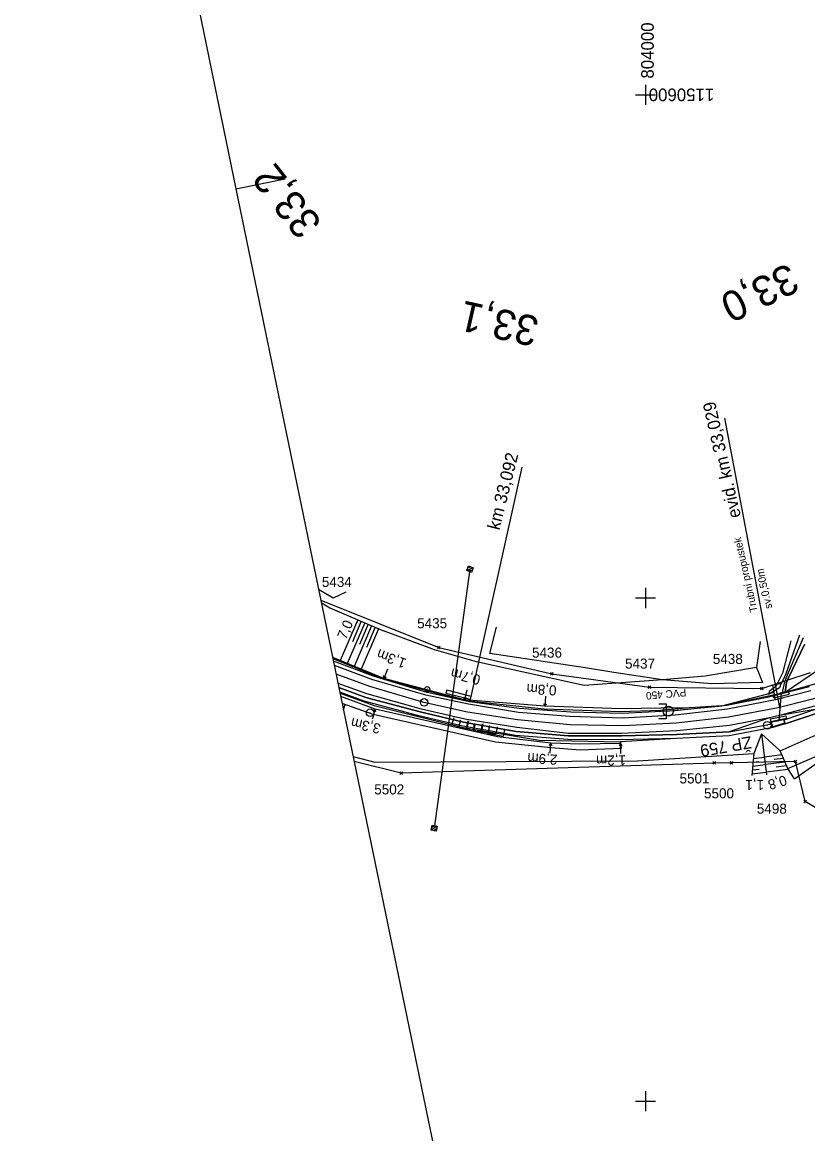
# Model space of a CAD drawing. Extents: x -804166 to -803706, y -1151030 to -1150147.
# Drawn here: x -804123.8 to -803967.8, y -1150806.5 to -1150585.6 of the extents above; entities that cross this region are included whole.
import ezdxf

# ---------------------------------------------------------------- set-up
doc = ezdxf.new("R2010")
doc.units = 0
for name, color, linetype in [('0381KM032-037P - Vrstva 1', 7, 'Continuous'), ('0381KM032-037P - Vrstva 11', 7, 'Continuous'), ('0381KM032-037P - Vrstva 13', 7, 'Continuous'), ('0381KM032-037P - Vrstva 16', 7, 'Continuous'), ('0381KM032-037P - Vrstva 17', 7, 'Continuous'), ('0381KM032-037P - Vrstva 19', 7, 'Continuous'), ('0381KM032-037P - Vrstva 25', 7, 'Continuous'), ('0381KM032-037P - Vrstva 4', 7, 'Continuous'), ('0381KM032-037P - Vrstva 43', 7, 'Continuous'), ('0381KM032-037P - Vrstva 44', 7, 'Continuous'), ('0381KM032-037P - Vrstva 48', 7, 'Continuous'), ('0381KM032-037P - Vrstva 49', 7, 'Continuous'), ('0381KM032-037P - Vrstva 7', 7, 'Continuous'), ('0381KM032-037P - Vrstva 9', 7, 'Continuous'), ('formát', 7, 'Continuous'), ('krizky_1000 - souradnice', 7, 'Continuous'), ('krizky_1000 - Vrstva 1', 7, 'Continuous'), ('szdc - hran DP', 7, 'Continuous'), ('szdc - szdc_cislo', 7, 'Continuous'), ('szdc - szdc_krizek', 7, 'Continuous'), ('vyt_sit - stávající', 7, 'Continuous')]:
    doc.layers.add(name, color=color, linetype=linetype)

msp = doc.modelspace()

# ---------------------------------------------------------------- linework, layer by layer
at = {"layer": '0381KM032-037P - Vrstva 1'}
msp.add_lwpolyline([(-803901.91, -1150682.6), (-803910.01, -1150690), (-803918.64, -1150696.78), (-803928.04, -1150703.06), (-803937.95, -1150708.69), (-803946.8, -1150712.93), (-803956.66, -1150716.87), (-803966.85, -1150720.1), (-803973.69, -1150721.81), (-803983.51, -1150723.68), (-803993.92, -1150724.91), (-804004.46, -1150725.42), (-804014.95, -1150725.21), (-804025.47, -1150724.25), (-804035.41, -1150722.67), (-804044.08, -1150720.74), (-804054.77, -1150717.61), (-804061.47, -1150715.14)], dxfattribs=at)
at = {"layer": '0381KM032-037P - Vrstva 11'}
for p, q in [((-804034.26, -1150693.99), (-804035.54, -1150694.57)), ((-804034.75, -1150693.8), (-804035.36, -1150694.08)), ((-804034.44, -1150694.48), (-804035.04, -1150694.76)), ((-804041.41, -1150745.38), (-804042.6, -1150746.13)), ((-804041.93, -1150745.26), (-804042.49, -1150745.62)), ((-804041.53, -1150745.9), (-804042.08, -1150746.25))]:
    msp.add_line(p, q, dxfattribs=at)
for points in [[(-804034.6, -1150694.92), (-804035.54, -1150694.57), (-804035.19, -1150693.64), (-804034.25, -1150693.98)], [(-804041.63, -1150746.35), (-804042.61, -1150746.13), (-804042.39, -1150745.16), (-804041.41, -1150745.38)]]:
    msp.add_lwpolyline(points, close=True, dxfattribs=at)
at = {"layer": '0381KM032-037P - Vrstva 13'}
for p, q in [((-804051.27, -1150714.14), (-804052.03, -1150715.99)), ((-804035.82, -1150720.44), (-804051.93, -1150716.22)), ((-804035.5, -1150718.26), (-804035.97, -1150720.21)), ((-804019.87, -1150719.5), (-804020.03, -1150721.49)), ((-804054.2, -1150724.02), (-804053.75, -1150722.07)), ((-803974.7, -1150725.77), (-803974.91, -1150725)), ((-803972.34, -1150724.85), (-803974.74, -1150725.59)), ((-803974.74, -1150725.59), (-803974.7, -1150725.77)), ((-803972.29, -1150725.01), (-803974.7, -1150725.77)), ((-803972.54, -1150724.23), (-803972.54, -1150724.26)), ((-803972.54, -1150724.26), (-803972.29, -1150725.01)), ((-803972.34, -1150724.85), (-803972.29, -1150725.01)), ((-804018.95, -1150730.84), (-804018.83, -1150728.85)), ((-804004.99, -1150728.9), (-804004.87, -1150729.93)), ((-804004.95, -1150730.9), (-804004.99, -1150728.9))]:
    msp.add_line(p, q, dxfattribs=at)
for points in [[(-803902.54, -1150686.99), (-803908.53, -1150691.68), (-803917.54, -1150698.65), (-803926.89, -1150705.06), (-803937, -1150710.49), (-803946.02, -1150714.66), (-803956.26, -1150718.85), (-803966.29, -1150722.19), (-803972.54, -1150724.26)], [(-803972.29, -1150725.01), (-803966.12, -1150722.97), (-803955.96, -1150719.58), (-803945.71, -1150715.38), (-803936.57, -1150711.19), (-803926.51, -1150705.78), (-803917.07, -1150699.31), (-803908.04, -1150692.29), (-803902.09, -1150687.65)], [(-804052.03, -1150715.99), (-804062.15, -1150711.83)], [(-804062.12, -1150712.02), (-804052.3, -1150716.03), (-804051.93, -1150716.22)], [(-804052.11, -1150715.42), (-804052.03, -1150715.99), (-804051.56, -1150715.64)], [(-803991.2, -1150721.8), (-803996.89, -1150721.92), (-804004.84, -1150722.06), (-804020.03, -1150721.49), (-804035.97, -1150720.21), (-804052.03, -1150715.99)], [(-804060.92, -1150717.79), (-804055.61, -1150719.76), (-804044.75, -1150722.66), (-804036.16, -1150724.67), (-804025.7, -1150726.54), (-804015.38, -1150727.38), (-804004.78, -1150727.4), (-803993.85, -1150727.11), (-803983.42, -1150726.57), (-803974.91, -1150725)], [(-803974.7, -1150725.77), (-803983.37, -1150727.37), (-803993.84, -1150727.91), (-804005.29, -1150728.22), (-804015.43, -1150728.15), (-804025.86, -1150727.31), (-804036.32, -1150725.46), (-804045.02, -1150723.43), (-804055.91, -1150720.49), (-804060.73, -1150718.71)], [(-804060.69, -1150718.95), (-804053.9, -1150721.4), (-804036.64, -1150725.7), (-804021.1, -1150728.28), (-804004.99, -1150728.61), (-804004.87, -1150729.93)], [(-804004.99, -1150728.9), (-804013.04, -1150729.07), (-804018.83, -1150728.85), (-804029.4, -1150727.62), (-804053.75, -1150722.07), (-804060.56, -1150719.58)], [(-804004.87, -1150729.93), (-804012.98, -1150730.26), (-804018.76, -1150729.81), (-804029.79, -1150728.64), (-804054.15, -1150723.15), (-804060.27, -1150720.94)], [(-804036.15, -1150719.65), (-804035.97, -1150720.21), (-804035.56, -1150719.79)], [(-803991.2, -1150721.8), (-803997.06, -1150722.33), (-804004.97, -1150722.65), (-804020.12, -1150722.09), (-804035.82, -1150720.44)], [(-804020.29, -1150720.97), (-804020.03, -1150721.49), (-804019.69, -1150721.02)], [(-804053.57, -1150722.62), (-804053.75, -1150722.07), (-804054.16, -1150722.49)], [(-803974.74, -1150725.59), (-803974.75, -1150725.58), (-803974.86, -1150725.17), (-803974.86, -1150725.17), (-803974.91, -1150725)], [(-803972.34, -1150724.85), (-803972.34, -1150724.85), (-803972.48, -1150724.42), (-803972.48, -1150724.42), (-803972.54, -1150724.26), (-803972.54, -1150724.23)], [(-804018.56, -1150729.36), (-804018.83, -1150728.85), (-804019.16, -1150729.33)], [(-804004.68, -1150729.4), (-804004.99, -1150728.9), (-804005.28, -1150729.41)], [(-804004.99, -1150728.9), (-804004.99, -1150728.9), (-804004.99, -1150728.9), (-804004.99, -1150728.61)]]:
    msp.add_lwpolyline(points, dxfattribs=at)
at = {"layer": '0381KM032-037P - Vrstva 16'}
msp.add_line((-803972.81, -1150718.81), (-803972.25, -1150718.74), dxfattribs=at)
for points in [[(-803969.39, -1150707.42), (-803972.15, -1150715.07), (-803972.68, -1150716.27), (-803973.1, -1150717.09), (-803973.4, -1150717.86), (-803975.59, -1150719.16)], [(-803972.81, -1150718.81), (-803972.31, -1150716.69), (-803971.8, -1150715.26), (-803968.63, -1150707.87)], [(-803971.15, -1150708.54), (-803972.82, -1150714.95), (-803974.15, -1150717.57), (-803975.48, -1150718.61), (-803975.59, -1150719.16)], [(-803968.41, -1150709.25), (-803971.62, -1150715.84), (-803971.99, -1150716.8), (-803972.25, -1150718.74)]]:
    msp.add_lwpolyline(points, dxfattribs=at)
at = {"layer": '0381KM032-037P - Vrstva 17'}
for points in [[(-804059.54, -1150698.86), (-804062.04, -1150700.07), (-804064.95, -1150698.29)], [(-803996.63, -1150716.3), (-804006.34, -1150714.83), (-804011.55, -1150713.97), (-804030.97, -1150711.02), (-804029.61, -1150705.83)], [(-803977.22, -1150708.65), (-803977.99, -1150713.83)], [(-803977.99, -1150713.83), (-803976.74, -1150716.79), (-803986.83, -1150717.08), (-803996.63, -1150716.3)]]:
    msp.add_lwpolyline(points, dxfattribs=at)
at = {"layer": '0381KM032-037P - Vrstva 19'}
for p, q in [((-803973.32, -1150721.76), (-803984.23, -1150664.27)), ((-803971.53, -1150718.65), (-803974.65, -1150719.35)), ((-803974.65, -1150719.35), (-803974.64, -1150719.23)), ((-803974.51, -1150719.84), (-803974.65, -1150719.35)), ((-803974.51, -1150719.84), (-803971.47, -1150719.15)), ((-803973.09, -1150718.93), (-803973.51, -1150724.35)), ((-803972.25, -1150718.74), (-803972.81, -1150718.81)), ((-803971.47, -1150719.15), (-803971.53, -1150718.65)), ((-803975.23, -1150724.05), (-803972.11, -1150723.39)), ((-803972.11, -1150723.39), (-803972.01, -1150723.98)), ((-803975.23, -1150724.05), (-803975.1, -1150724.59)), ((-803972.01, -1150723.98), (-803975.1, -1150724.59)), ((-803974.91, -1150725), (-803975.1, -1150724.59)), ((-803974.91, -1150725), (-803974.9, -1150724.64)), ((-803974.91, -1150725), (-803974.91, -1150725))]:
    msp.add_line(p, q, dxfattribs=at)
for points in [[(-803974.64, -1150719.23), (-803973.09, -1150718.93), (-803972.81, -1150718.81)], [(-803975.1, -1150724.59), (-803974.9, -1150724.64), (-803973.51, -1150724.35), (-803972.67, -1150724.15), (-803972.01, -1150723.98)]]:
    msp.add_lwpolyline(points, dxfattribs=at)
for centre, major_axis, ratio, start_param, end_param in [((-803973.07, -1150718.94), (-0.255, -0.028), 0.056503, 4.768181, 7.86041), ((-803973.09, -1150718.94), (-0.255, -0.028), 0.056457, 1.624991, 4.720578), ((-803973.51, -1150724.33), (0.232, 0.091), 0.052847, 1.520766, 4.668999), ((-803973.51, -1150724.33), (0.232, 0.091), 0.052921, 4.661932, 7.811186)]:
    msp.add_ellipse(centre, major_axis=major_axis, ratio=ratio, start_param=start_param, end_param=end_param, dxfattribs=at)
at = {"layer": '0381KM032-037P - Vrstva 25'}
msp.add_line((-804034.9, -1150694.28), (-804042.01, -1150745.75), dxfattribs=at)
at = {"layer": '0381KM032-037P - Vrstva 4'}
msp.add_line((-803966.29, -1150722.19), (-803973.38, -1150723.34), dxfattribs=at)
for points in [[(-803967.41, -1150717.64), (-803975.82, -1150719.77), (-803983.88, -1150721.36), (-803994.18, -1150722.4), (-804004.64, -1150722.95), (-804014.86, -1150722.69), (-804025.14, -1150721.99), (-804034.98, -1150720.62), (-804043.41, -1150718.77), (-804051.93, -1150716.22), (-804054.24, -1150715.48), (-804062, -1150712.59)], [(-803967.18, -1150718.43), (-803974.22, -1150720.27), (-803983.73, -1150722.13), (-803994.13, -1150723.26), (-804004.52, -1150723.87), (-804015.05, -1150723.54), (-804025.27, -1150722.78), (-804035.17, -1150721.13), (-804043.67, -1150719.32), (-804054.39, -1150716.19), (-804061.83, -1150713.39)], [(-803966.45, -1150721.53), (-803973.38, -1150723.34), (-803975.35, -1150723.79), (-803983.32, -1150725.37), (-803993.82, -1150726.43), (-804004.8, -1150726.96), (-804015.29, -1150726.92), (-804025.6, -1150725.76), (-804035.88, -1150724.11), (-804044.5, -1150722.13), (-804055.4, -1150719.07), (-804061.09, -1150716.98)], [(-803975.35, -1150723.79), (-803983.42, -1150726.57), (-803993.85, -1150727.11), (-804004.78, -1150727.4), (-804015.38, -1150727.38), (-804025.7, -1150726.54), (-804036.16, -1150724.67), (-804044.75, -1150722.66), (-804055.61, -1150719.76), (-804060.92, -1150717.79)]]:
    msp.add_lwpolyline(points, dxfattribs=at)
at = {"layer": '0381KM032-037P - Vrstva 43'}
for points in [[(-803972.71, -1150719.94), (-803974.19, -1150720.21), (-803974.72, -1150717.26), (-803973.25, -1150716.99)], [(-803997.39, -1150721.01), (-803995.89, -1150721.01), (-803995.89, -1150724.01), (-803997.39, -1150724.01)], [(-804035.17, -1150724.55), (-804035.58, -1150726), (-804038.46, -1150725.19), (-804038.06, -1150723.74)], [(-804033.84, -1150725), (-804034.23, -1150726.45), (-804037.12, -1150725.67), (-804036.73, -1150724.22)], [(-804032.32, -1150725.04), (-804032.63, -1150726.51), (-804035.56, -1150725.9), (-804035.26, -1150724.43)], [(-804031.05, -1150725.35), (-804031.24, -1150726.84), (-804034.22, -1150726.45), (-804034.02, -1150724.96)], [(-804029.49, -1150725.62), (-804029.77, -1150727.09), (-804032.72, -1150726.52), (-804032.43, -1150725.05)], [(-804028.05, -1150726.05), (-804028.31, -1150727.53), (-804031.27, -1150727.01), (-804031.01, -1150725.53)]]:
    msp.add_lwpolyline(points, dxfattribs=at)
msp.add_circle((-803995.51, -1150722.5), 1, dxfattribs=at)
at = {"layer": '0381KM032-037P - Vrstva 44'}
msp.add_lwpolyline([(-803995.89, -1150722.51), (-803984.82, -1150721.44), (-803974.46, -1150718.74)], dxfattribs=at)
at = {"layer": '0381KM032-037P - Vrstva 48'}
for p, q in [((-804057.18, -1150704.34), (-804060.65, -1150712.45)), ((-804055.8, -1150704.93), (-804059.26, -1150713.02)), ((-804056.49, -1150704.63), (-804058.22, -1150708.69)), ((-804054.42, -1150705.52), (-804057.88, -1150713.59)), ((-804055.11, -1150705.22), (-804056.84, -1150709.27)), ((-804053.04, -1150706.11), (-804056.49, -1150714.16)), ((-804053.73, -1150705.81), (-804055.46, -1150709.84)), ((-804060.03, -1150722.14), (-804059.67, -1150721.16)), ((-803978.65, -1150732.65), (-803977.48, -1150732.51)), ((-803978.58, -1150731.89), (-803976.4, -1150731.62)), ((-803972.9, -1150731.19), (-803976.4, -1150731.62)), ((-803972.3, -1150732.62), (-803976.22, -1150733.11)), ((-803972.6, -1150731.91), (-803974.46, -1150732.13)), ((-803978.85, -1150734.94), (-803976.04, -1150734.6)), ((-803978.79, -1150734.18), (-803977.46, -1150734.02)), ((-803978.72, -1150733.42), (-803976.22, -1150733.11)), ((-803971.67, -1150734.06), (-803976.04, -1150734.6)), ((-803972, -1150733.34), (-803974.07, -1150733.6))]:
    msp.add_line(p, q, dxfattribs=at)
at = {"layer": '0381KM032-037P - Vrstva 49'}
for p, q in [((-803976.97, -1150726.99), (-803978.5, -1150730.91)), ((-803976.97, -1150726.99), (-803975.97, -1150735.13)), ((-803976.97, -1150726.99), (-803973.24, -1150730.36)), ((-804001.62, -1150732.39), (-803978.5, -1150730.91)), ((-803978.5, -1150730.91), (-803978.89, -1150735.31))]:
    msp.add_line(p, q, dxfattribs=at)
for points in [[(-803984.82, -1150721.44), (-803974.64, -1150719.23), (-803973.09, -1150718.93), (-803972.81, -1150718.81), (-803972.25, -1150718.74), (-803965.21, -1150716.75), (-803957.6, -1150714.53), (-803947.89, -1150710.4), (-803939.16, -1150706.21), (-803931.83, -1150702.12), (-803924.09, -1150697.22), (-803916.61, -1150691.84), (-803910.08, -1150686.51), (-803906.52, -1150683.39), (-803903.6, -1150681.32)], [(-803972.25, -1150718.74), (-803965.84, -1150714.34), (-803956.6, -1150711.22), (-803948.84, -1150707.73), (-803941.39, -1150704.08), (-803932.78, -1150700.06), (-803925.79, -1150694.95), (-803918.15, -1150689.68), (-803911.55, -1150684.9), (-803903.6, -1150681.32)], [(-803902.09, -1150687.65), (-803908.04, -1150692.29), (-803917.07, -1150699.31), (-803926.51, -1150705.78), (-803936.57, -1150711.19), (-803945.71, -1150715.38), (-803955.96, -1150719.58), (-803966.12, -1150722.97), (-803972.29, -1150725.01), (-803974.7, -1150725.77), (-803983.37, -1150727.37), (-803993.84, -1150727.91), (-804004.99, -1150728.61), (-804004.87, -1150729.93), (-804012.98, -1150730.26), (-804018.76, -1150729.81), (-804029.79, -1150728.64), (-804054.15, -1150723.15), (-804060.27, -1150720.94)], [(-803973.24, -1150730.36), (-803966.72, -1150727.46), (-803955.16, -1150723.59), (-803942.54, -1150718.42), (-803927.91, -1150711.46), (-803917.77, -1150704.05), (-803910.65, -1150697.21), (-803903.52, -1150690.49), (-803900.1, -1150686.57)], [(-803970.39, -1150735.93), (-803964.35, -1150731.61), (-803955.1, -1150727.23), (-803941.08, -1150721.95), (-803928.21, -1150715.68), (-803916.07, -1150708.06), (-803913.5, -1150704.53), (-803910.65, -1150697.21)], [(-804064.42, -1150700.87), (-804062.72, -1150701.97), (-804052.08, -1150706.52)], [(-803971.76, -1150733.92), (-803964.99, -1150730.97), (-803955.15, -1150726.85), (-803941.3, -1150721.62), (-803928.58, -1150715.41), (-803917.05, -1150707.62), (-803913.5, -1150704.53)], [(-803977.22, -1150708.65), (-803977.99, -1150713.83), (-803988.17, -1150715.55), (-803996.63, -1150716.3), (-804012.18, -1150717.41), (-804033.61, -1150712.69), (-804041.95, -1150710.32), (-804052.08, -1150706.52)], [(-803972.25, -1150718.74), (-803971.99, -1150716.8), (-803971.62, -1150715.84), (-803968.41, -1150709.25)], [(-804062.15, -1150711.83), (-804052.03, -1150715.99)], [(-803984.82, -1150721.44), (-803991.2, -1150721.8), (-803996.89, -1150721.92), (-804004.84, -1150722.06), (-804020.03, -1150721.49), (-804035.97, -1150720.21), (-804052.03, -1150715.99)], [(-803970.39, -1150735.93), (-803971.76, -1150733.92), (-803973.24, -1150730.36)], [(-804058.09, -1150731.52), (-804053.81, -1150732.63), (-804001.62, -1150732.39)]]:
    msp.add_lwpolyline(points, dxfattribs=at)
at = {"layer": '0381KM032-037P - Vrstva 7'}
msp.add_line((-804043.32, -1150718.13), (-804043.42, -1150718.1), dxfattribs=at)
for centre, radius in [((-804043.37, -1150718.12), 0.5), ((-804043.99, -1150720.76), 0.75)]:
    msp.add_circle(centre, radius, dxfattribs=at)
at = {"layer": '0381KM032-037P - Vrstva 9'}
for p, q in [((-804034.8, -1150720.15), (-804024.5, -1150674.02)), ((-804039.51, -1150718.34), (-804039.66, -1150718.92)), ((-804039.66, -1150718.92), (-804034.81, -1150720.14)), ((-804034.66, -1150719.56), (-804039.51, -1150718.34)), ((-804034.66, -1150719.56), (-804034.52, -1150718.98)), ((-804034.81, -1150720.14), (-804034.66, -1150719.56))]:
    msp.add_line(p, q, dxfattribs=at)
at = {"layer": 'formát'}
for p, q in [((-804123.84, -1150413.06), (-804081.38, -1150618.72)), ((-804081.38, -1150618.72), (-804071.58, -1150616.7)), ((-804081.38, -1150618.72), (-803996.46, -1151030.05))]:
    msp.add_line(p, q, dxfattribs=at)
at = {"layer": 'krizky_1000 - Vrstva 1'}
for points in [[(-804002, -1150600), (-803998, -1150600)], [(-804000, -1150598), (-804000, -1150602)], [(-804000, -1150698), (-804000, -1150702)], [(-804002, -1150700), (-803998, -1150700)], [(-804000, -1150798), (-804000, -1150802)], [(-804002, -1150800), (-803998, -1150800)]]:
    msp.add_lwpolyline(points, dxfattribs=at)
at = {"layer": 'szdc - hran DP'}
for p, q in [((-804064.5, -1150700.47), (-804041.05, -1150709.83)), ((-804041.05, -1150709.83), (-804018.63, -1150715.09)), ((-803976.9, -1150717.98), (-803967.26, -1150714.81)), ((-804018.63, -1150715.09), (-803999.22, -1150717.72)), ((-803999.22, -1150717.72), (-803976.9, -1150717.98)), ((-804048.58, -1150734.81), (-804057.89, -1150732.49)), ((-803970.22, -1150732.49), (-803982.91, -1150732.74)), ((-803968.3, -1150740.45), (-803970.22, -1150732.49)), ((-803986.36, -1150732.8), (-804048.58, -1150734.81)), ((-803982.91, -1150732.74), (-803986.36, -1150732.8)), ((-803963.98, -1150743), (-803968.3, -1150740.45))]:
    msp.add_line(p, q, dxfattribs=at)
at = {"layer": 'szdc - szdc_krizek'}
for p, q in [((-804040.79, -1150710.09), (-804041.32, -1150709.56)), ((-804041.32, -1150710.09), (-804040.79, -1150709.56)), ((-804018.36, -1150715.35), (-804018.9, -1150714.82)), ((-804018.9, -1150715.35), (-804018.36, -1150714.82)), ((-803998.96, -1150717.99), (-803999.49, -1150717.46)), ((-803999.49, -1150717.99), (-803998.96, -1150717.46)), ((-803976.64, -1150718.25), (-803977.17, -1150717.72)), ((-803977.17, -1150718.25), (-803976.64, -1150717.72)), ((-803986.09, -1150733.06), (-803986.63, -1150732.53)), ((-803986.63, -1150733.06), (-803986.09, -1150732.53)), ((-803982.65, -1150733.01), (-803983.18, -1150732.48)), ((-803983.18, -1150733.01), (-803982.65, -1150732.48)), ((-803969.96, -1150732.76), (-803970.49, -1150732.23)), ((-803970.49, -1150732.76), (-803969.96, -1150732.23)), ((-804048.32, -1150735.07), (-804048.85, -1150734.54)), ((-804048.85, -1150735.07), (-804048.32, -1150734.54)), ((-803968.04, -1150740.72), (-803968.57, -1150740.19)), ((-803968.57, -1150740.72), (-803968.04, -1150740.19))]:
    msp.add_line(p, q, dxfattribs=at)
at = {"layer": 'vyt_sit - stávající'}
for p, q in [((-804054.77, -1150722.82), (-804054.67, -1150722.82)), ((-803975.87, -1150725.31), (-803975.77, -1150725.31))]:
    msp.add_line(p, q, dxfattribs=at)
for centre in [(-804054.72, -1150722.82), (-803975.82, -1150725.31)]:
    msp.add_circle(centre, 0.756, dxfattribs=at)

# ---------------------------------------------------------------- texts
at = {"layer": '0381KM032-037P - Vrstva 13'}
for s, rotation, p in [('1,3m', 159.4135, (-804047.36, -1150712.19)), ('0,7m', 165.6438, (-804032.66, -1150715.41)), ('0,8m', 176.7126, (-804017.65, -1150717.4)), ('3,3m', 167.1636, (-804052.49, -1150725.09)), ('2,9m', 176.4791, (-804017.48, -1150731.17)), ('1,2m', 181.2027, (-804003.91, -1150731.23))]:
    msp.add_text(s, height=2, rotation=rotation, dxfattribs=at).set_placement(p)
at = {"layer": '0381KM032-037P - Vrstva 19'}
for s, height, p in [('evid. km 33,029', 2.5, (-803981.04, -1150683.82)), ('Trubní propustek', 1.5, (-803977.75, -1150702.64)), ('sv.0,50m', 1.5, (-803974.83, -1150701.98))]:
    msp.add_text(s, height=height, rotation=102.69, dxfattribs=at).set_placement(p)
at = {"layer": '0381KM032-037P - Vrstva 43'}
msp.add_text('PVC 450', height=1.5, rotation=185, dxfattribs=at).set_placement((-803991.99, -1150718.03))
at = {"layer": '0381KM032-037P - Vrstva 48'}
for s, rotation, p in [('7,0', 66.8248, (-804059.51, -1150708.39)), ('1,1', 179.9545, (-803976.45, -1150736.17)), ('0,8', 197.0064, (-803972.32, -1150735.18))]:
    msp.add_text(s, height=2, rotation=rotation, dxfattribs=at).set_placement(p)
at = {"layer": '0381KM032-037P - Vrstva 7'}
for s, rotation, p in [('33,2', 128.139, (-804064.09, -1150625.46)), ('33,0', 205.6225, (-803971.56, -1150633.32)), ('33,1', 167.4012, (-804020.85, -1150644.28))]:
    msp.add_text(s, height=6, rotation=rotation, dxfattribs=at).set_placement(p)
at = {"layer": '0381KM032-037P - Vrstva 9'}
msp.add_text('km 33,092', height=2.5, rotation=75.8763, dxfattribs=at).set_placement((-804029.06, -1150686.64))
at = {"layer": 'krizky_1000 - souradnice'}
for s, rotation, p in [('804000', 90, (-803998.38, -1150596.79)), ('1150600', 180, (-803986.36, -1150598.77))]:
    msp.add_text(s, height=2.5, rotation=rotation, dxfattribs=at).set_placement(p)
at = {"layer": 'szdc - szdc_cislo'}
for s, p in [('5434', (-804064.31, -1150697.81)), ('5435', (-804045.38, -1150706.02)), ('5436', (-804022.56, -1150711.86)), ('5437', (-804004.08, -1150714.04)), ('5438', (-803986.64, -1150713.12)), ('5501', (-803993.25, -1150736.86)), ('5502', (-804053.9, -1150739.04)), ('5500', (-803988.39, -1150739.82)), ('5498', (-803977.89, -1150742.87))]:
    msp.add_text(s, height=2, dxfattribs=at).set_placement(p)
at = {"layer": 'vyt_sit - stávající'}
msp.add_text('ŽP 759', height=2.4, rotation=190, dxfattribs=at).set_placement((-803979.13, -1150727.45))

doc.saveas('drawing.dxf')
